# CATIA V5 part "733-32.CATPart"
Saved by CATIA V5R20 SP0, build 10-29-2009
Part number: 733-32
Bounding box of the stored display mesh (mm): x -28 to 28, y -28 to 28, z -30 to 63
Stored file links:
  C:\Users\Utente\Desktop\IO LAVORO\3D X SITO CF\X SITO\733\733-32.CATPart
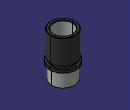
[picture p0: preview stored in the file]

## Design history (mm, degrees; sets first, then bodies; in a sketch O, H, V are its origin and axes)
Set1
  DatumSurface1 to DatumSurface25 "733-32"
Body1 (main body)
